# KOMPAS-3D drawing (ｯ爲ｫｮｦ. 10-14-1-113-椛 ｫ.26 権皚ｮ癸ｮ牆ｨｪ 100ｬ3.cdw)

Views: Вид А, Вид Б, Вид 1, Вид 2, Вид 3, Вид 5
Referenced files: КМ-3.cdw
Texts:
  АС Маша
  ООО Северный Стандарт
  Текст на чертеже
  Размерные надписи
  Шероховатость
  Линия-выноска #1
  Линия-выноска #2
  Линия-выноска #3
  Отклонения формы и база
  Заголовок таблицы
  Ячейка таблицы
  Стрелка вида
  Обозначение изменения
  Фигурная скобка
  Номер узла
  Марка координационной оси
  VRCB
  Выносная надпись
  Обозначение узла
  Марка/позиционное обозначение с линией-выноской
  Марка/позиционное обозначение на линии
  Марка/позиционное обозначение без линии-выноски
  Normal
  txt
  Body Text
  heading 1
  Знак Знак Знак Знак Знак Знак
  Verdana
  Лит-Масса-Масштаб
  Материал-Предприятие
  MS Sans Serif
  Simplex
  Txt
  Title Specification
  Body Specification ( left align )
  Body Specificaton ( centered )
  Без имени
  TXT
  Additional DXF text style 0
  Обычный
  Термин
  Список определений
  Адрес
  Цитаты
  Форматированный
  Courier New
  Z-конец формы
  Z-начало формы
  ТекстШаг1
  ООббыыччнныыйй
  Definition Term
  Definition List
  Address
  Blockquote
  Preformatted
  z-Bottom of Form
  z-Top of Form
  ISOCP
  Денис
  Title
  header
  heading 2
  AGOpus
  footer
  HeliosLight
  Pa3
  Pa1
  ссылки
  Подпись в квадратике
  табл
  цепи
  Маркировка
  клеммы, контакты
  тексты табл
  Тексты. 3,2
  ЗОНА_привяз
  текст переноса
  ТТееррммиинн
  ССппииссоокк ооппррееддееллеенниийй
  ААддрреесс
  ЦЦииттааттыы
  ФФооррммааттиирроовваанннныыйй
  Z-ккооннеецц ффооррммыы
  Z-ннааччааллоо ффооррммыы
  GOST 2.304 type A
  rustxt
  heading 8
  heading 3
  heading 6
  heading 7
  russ
  Абзац Знак
  heading 4
  heading 5
  heading 9
  Body Text 3
  Шрифт 2.5
  Заголовки
  RUSTXT
  ISOCPEUR
  FR5
  Tahoma
  Table Heading
  Table Contents
  маркировка
  NormalParagraphStyle
  ESK - Обозначение
  ГОСТ_МНЕ
  II 5
  Iiaioieo 4
  Ioieo 3
  Iia?acaae 2
  ?acaae 1
  Ciae Ciae Ciae Ciae Ciae Ciae
  MONOMAKH
  Heading
  HiddenHorzOCl
  CM2
  CM7
  CM3
  CM4
  CM8
  CM9
  style2
  Три с половиной
  Aioiaue
  Courier New Cyr
  CNBNDG+TimesNewRoman
  Subtitle
  Текст 3,5
  Helvetica
  CM97
  CM93
  Спецификация к схеме расположения резервуара
  Примечания:
  1. См. совместно с чертежом 10/14-1-113-КС, л.3
  2. Крутизну откосов котлована заложить согласно 10/14-1-ГИ2. Работы вести в сухом котловане.
  3. При опирании на грунт центральный угол охвата резервуара песчаной подготовкой должен быть90 .
  4. Над резервуаром на поверхности земли помимо собственного веса грунта не допускаются иные
  постоянные или подвижные нагрузки.
  5. Анкерные болты свай срезать.
  6. Материал металлоконструкций - сталь С 345-1 по ГОСТ 27772-88*. Сварку выполнять по
  ГОСТ 5264-80* в соответствии с требованиями СНиП 3.03.01-87 электродами Э-50А по ГОСТ 9467-75*.
  7. Поверхности металлических элементов, соприкасающиеся с грунтом, покрыть слоем мастики
  изоляционной, битумно-резиновой марки МБР-90, ГОСТ 15836-79, по слою грутновки ГТ-760 ИН,
  ТУ 102-340-83. Качество лакокрасочного покрытия должно соответствовать VI классу по
  ГОСТ 9.032-74*(см.п.5.19 СНиП 2.03.11-85). Антикоррозийную защиту внутренних поверхностей
  резервуара выполнить эмалью ХС-5132 по ТУ 6-10-11-19-12-79.
  8. Место сопряжения маслосборника с маслопроводом уточнить по месту. В качестве соединительного
  элемента применить трубу стальную  377 ГОСТ 10704-91 в теплоизоляции 100мм. Места стыковки
  труб герметизировать. Стыковку трубы с маслосборником выполнить сваркой с последующей защитой
  открытых металлических частей соединения от коррозии. Соединение  труб ЧНР 300 с металлическим
  резервуаром осуществляется согласно пункта 3.44 СНиП 3.05-04-85 с помощью стального сварного
  патрубка (трубы стальные электросварные прямошовные по ГОСТ 10704-91), труба входит
  в маслосборник на отметке 98,82) (см. 10/14-1-028-НК, л.3);
  9. Мероприятия по утеплению корпуса проводит завод-изготовитель резервуара. В данном случае это
  будет двойной утепленный корпус, состоящий из двух стальных стенок, между которыми располагается
  утеплитель (минеральная вата на основе базальтового волокна).
  10. Обратную засыпку котлована производить песком средней крупности с послойным уплотнением.
  11. Относительная отметка 0,000 соответствует абсолютной отметке 100,00.
  12. В целях снижения касательных сил морозного пучения грунта предусмотреть обмазку части свай
  расположенной в зоне сезонного промерзания кремнийорганической эмалью КО-174 по ТУ II-93-67.
  13. Место сопряжения маслосборника с напорным трубопроводом подачи стоков ( 63) уточнить по месту.
  В качестве соединительного элемента применить трубу стальную  73 ГОСТ 10704-91 в теплоизоляции.
  Места стыковки труб герметизировать. Стыковку трубы с маслосборником выполнить сваркой
  с последующей защитой открытых металлических частей соединения от коррозии. Соединение труб ПЭ80
  GreekC
  полиэтилен сталь (переходник ПЭ-сталь 63/57) Труба входит в маслосборник на отметке 98,75).
  14. Границы котлована показаны без учета конструкций крепления стенок. Схему монтажа маслосборника
  см. 10/14-1-ПОС л.7.
  Стенка резервуара
  маслосборника
  Труба чугунная ЧНР  300
  маслопровода
  Стальная труба
  Марка,
  поз.
  Кол.
  ед. кг
  ГОСТ 5915-70*
  ГОСТ 11371-78*
  Балка Б1
  Хомут Х-1
  Гайка М30
  Шайба М30
  Резервуар
  Свая С35.10-1
  Подсыпка из среднезернистого песка с
  Отмостка из
  асфальто-бетона
  Схема расположения резервуара
  См. примеч. п.8
  См. примеч. п.13
  Труба напорная ПЭ 80  63
  сваи
  послойным уплотнением до плотности 1,65 т/м3
  Закладная деталь
  ACAD_ISO10W100_RGB_0_0_0_SC_0.25_THICK_0.25
  ACAD_ISO04W100_RGB_0_0_0_SC_1_THICK_0.25
  ACAD_ISO10W100_RGB_0_0_0_SC_1_THICK_0.25
  ACAD_ISO10W100_RGB_0_0_0_SC_0.5_THICK_0.25
  ACAD_ISO10W100_RGB_255_0_0_SC_0.25_THICK_0.25
  СONTINUOUS_RGB_255_0_0_THICK_0.25
  POLYLINE_STYLE_0.25_RGB_40_0_0
  POLYLINE_STYLE_0.40_RGB_0_0_0
  ACAD_ISO10W100_RGB_40_0_0_SC_0.25_THICK_0.25
  ACAD_ISO04W100_RGB_40_0_0_SC_1_THICK_0.25
  ACAD_ISO10W100_RGB_40_0_0_SC_1_THICK_0.25
  AR-SAND
  AR-SAND 0
  AR-SAND 1
  AR-SAND 2
  AR-SAND 3
  Стили документа
  Н. контр
  Шашерин
  Маслосборник V=100м 3
  Королева
  Разраб.
  Реконструкция ПС 110 кВ Опорная
  (замена трансформаторов 16МВА на 40МВА)
  Схема энергетическая функциональная
  Галактионов
Dimensions and other numbers on the sheet: 10/14-1-113-КС; 7; 3.5; 2.5; 2,5; 1,8; 3,2_; 3,2; 2,5 (контакты, клеммы); 3,2 (надписи); 3,2 (Зоны); 5; 2,5_01; 2,5_3; 3,5_01; 3,5_tabl; 5_заголовок; 2,3_; 3,2_зона не привяз; 3,5; 3.2 маркировка; 3,2 элементы; 3,2 линия; 3,2 таблица; 2,5 грязносинь; 2.5 курсив; 2.5_Э5_надписи; 2.5_Э5_ссылки; 2.5_кабель; 3.2; 2.5 надписи; 3.2 фиол; 5,0_белый_подчёркнутый; 3 и 5; 3.2 (текст); -0.530; -1.080; 200; 1; 10/14-1-113-КС.И-12; 3; 24; 12; 6; 416,6; 94,1; 0,24; 0,05; 5902; 1249,8; 282,3; 670; 1900; 2-2; 250; +0.250; 4; 0.000; 5140; -3.650; -4.350; 1000; 700; 1400; 3800; 3650; 350; 4350; -1,080; 4150; 1650; 3300; 12000; 2; 880; 820; 13700; 1800; 620; 1-1; 4000; 2200; 950; 4380; 4335; 1195; 75; 450; 1:25; 11.12; 06.08/86.002-КМ-; 26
